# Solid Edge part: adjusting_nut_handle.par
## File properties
Title: Adjusting nut handle
Author: vicky Raina
Template: Normal.par
Last saved by: TIET
Revision: 11
Application: Solid Edge
Density: 0 kg/mm^3
Accuracy: 0.99
Material: aluminum
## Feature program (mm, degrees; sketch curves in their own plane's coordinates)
sketch for "unnamed Protrusion 1" plane through (0, 0, 0) normal (0, -1, 0) x-axis (1, 0, 0)
  circle centre (0, 0) radius 9.5123
extrude "unnamed Protrusion 1" add finite 127 symmetric
chamfer "Chamfer_1" setback 1.5748
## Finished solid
Body 1: solid body, 5 faces, 4 edges, 0 vertices.
  Faces by surface: cone 2, plane 2, cylinder 1
  Edges by curve: circle 4
Bounding box of the edges (mm): 19.025 x 127.000 x 19.025, from (-9.5123, -63.5, -9.5123) to (9.5123, 63.5, 9.5123).
Cylindrical faces by radius (mm): R9.5123 x1
Conical faces (half-angle, radius in mm at the cone's reference point): 45 deg R7.9375 x1, 45 deg R9.5123 x1
Planar faces by outward normal: +y 1, -y 1
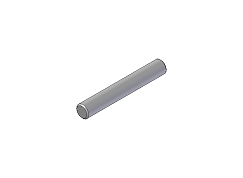
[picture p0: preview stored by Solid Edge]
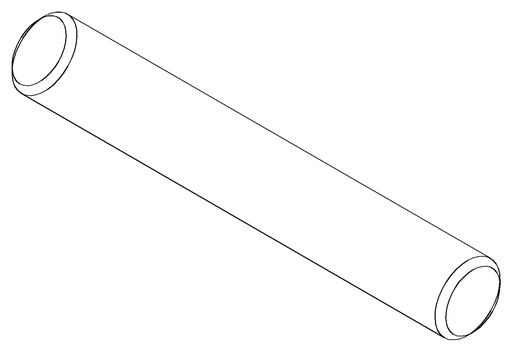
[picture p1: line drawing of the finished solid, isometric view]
